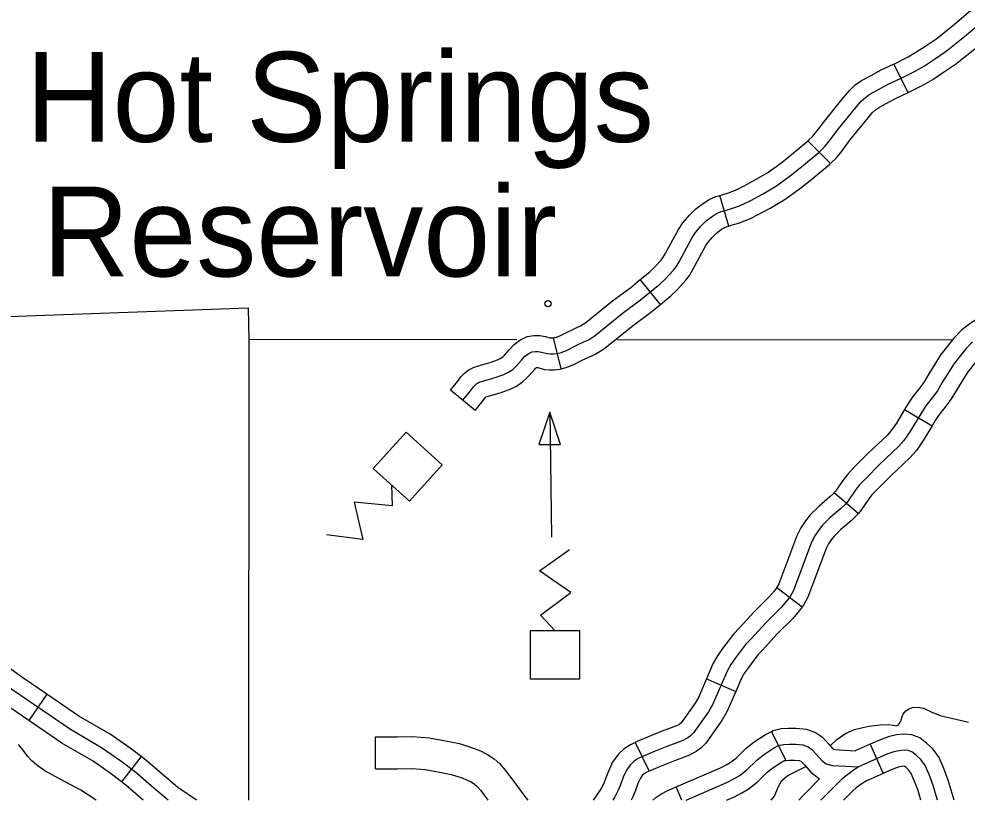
# Model space of a CAD drawing. Extents: x -3711 to 825, y -151 to 1050.
# Drawn here: x -2609.55 to -2559.63, y 120.35 to 161.5 of the extents above; entities that cross this region are included whole.
import ezdxf

# ---------------------------------------------------------------- set-up
doc = ezdxf.new("R2010")
doc.units = 0
for name, color, linetype in [('Level 32', 7, 'Continuous'), ('Level 35', 7, 'Continuous'), ('Level 4', 7, 'Continuous'), ('Level 46', 7, 'Continuous'), ('Level 5', 7, 'Continuous'), ('Level 57', 7, 'Continuous')]:
    doc.layers.add(name, color=color, linetype=linetype)

msp = doc.modelspace()

# ---------------------------------------------------------------- linework, layer by layer
at = {"layer": 'Level 32'}
for p, q in [((-2562.72, 157.628), (-2563.48, 159.128)), ((-2566.815, 153.885), (-2568.004, 155.074)), ((-2572.176, 150.593), (-2572.638, 152.21)), ((-2575.77, 146.466), (-2576.831, 147.77)), ((-2581.001, 143.07), (-2581.409, 144.701)), ((-2585.52, 140.884), (-2586.819, 141.951)), ((-2562.913, 140.934), (-2561.469, 140.074)), ((-2566.618, 136.552), (-2565.347, 135.452)), ((-2569.649, 131.545), (-2568.311, 130.529)), ((-2573.353, 126.732), (-2571.809, 126.066)), ((-2608.085, 125.936), (-2609.037, 124.549)), ((-2569.173, 122.47), (-2569.925, 123.974)), ((-2577.102, 123.391), (-2576.374, 121.876)), ((-2564.732, 123.296), (-2564.052, 121.758)), ((-2603.12, 122.647), (-2604.142, 121.312)), ((-2574.653, 120.355), (-2574.948, 121.043))]:
    msp.add_line(p, q, dxfattribs=at)
for points in [[(-2563.48, 159.128), (-2562.72, 159.514), (-2562.318, 159.749), (-2561.801, 160.091), (-2561.227, 160.48), (-2560.289, 161.231), (-2559.321, 162.053), (-2558.906, 162.446)], [(-2586.169, 141.418), (-2585.769, 141.905), (-2585.618, 142.121), (-2585.531, 142.219), (-2585.434, 142.294), (-2585.272, 142.381), (-2584.818, 142.511), (-2584.418, 142.63), (-2584.018, 142.77), (-2583.78, 142.889), (-2583.553, 143.041), (-2583.369, 143.214), (-2583.088, 143.528), (-2582.904, 143.734), (-2582.731, 143.863), (-2582.525, 143.961), (-2582.352, 143.993), (-2582.212, 143.993), (-2582.028, 143.95), (-2581.736, 143.874), (-2581.585, 143.863), (-2581.401, 143.863), (-2581.206, 143.885), (-2580.99, 143.939), (-2580.687, 144.058), (-2580.309, 144.253), (-2580.028, 144.394), (-2579.768, 144.513), (-2579.595, 144.588), (-2579.39, 144.707), (-2579.195, 144.837), (-2577.779, 145.984), (-2576.816, 146.699), (-2575.778, 147.543), (-2575.497, 147.813), (-2575.081, 148.266), (-2574.946, 148.453), (-2574.791, 148.712), (-2574.102, 149.988), (-2573.929, 150.259), (-2573.638, 150.584), (-2573.356, 150.865), (-2573.032, 151.115), (-2572.814, 151.249), (-2572.576, 151.353), (-2572.287, 151.436), (-2571.924, 151.55), (-2571.659, 151.644), (-2571.378, 151.763), (-2571.01, 151.947), (-2570.405, 152.272), (-2569.659, 152.715), (-2568.848, 153.3), (-2568.231, 153.808), (-2567.41, 154.479), (-2567.128, 154.761), (-2566.869, 155.074), (-2566.458, 155.626), (-2565.647, 156.644), (-2565.215, 157.152), (-2564.98, 157.371), (-2564.739, 157.542), (-2564.285, 157.791), (-2563.777, 158.061), (-2563.128, 158.364), (-2562.317, 158.775), (-2561.874, 159.035), (-2561.333, 159.392), (-2560.727, 159.803), (-2559.754, 160.583), (-2558.76, 161.427)], [(-2562.72, 157.628), (-2561.914, 158.037), (-2561.429, 158.321), (-2560.865, 158.694), (-2560.228, 159.127), (-2559.22, 159.934), (-2558.198, 160.8), (-2557.75, 161.225)], [(-2568.004, 155.074), (-2567.751, 155.327), (-2567.53, 155.594), (-2567.124, 156.139), (-2566.296, 157.178), (-2565.824, 157.734), (-2565.512, 158.024), (-2565.185, 158.256), (-2564.684, 158.53), (-2564.152, 158.814), (-2563.496, 159.12), (-2563.481, 159.128)], [(-2566.815, 153.885), (-2566.506, 154.194), (-2566.207, 154.555), (-2565.792, 155.113), (-2564.998, 156.109), (-2564.606, 156.571), (-2564.448, 156.718), (-2564.292, 156.828), (-2563.885, 157.051), (-2563.401, 157.309), (-2562.76, 157.608), (-2562.72, 157.628)], [(-2572.638, 152.21), (-2572.528, 152.241), (-2572.191, 152.347), (-2571.964, 152.428), (-2571.73, 152.527), (-2571.397, 152.693), (-2570.818, 153.004), (-2570.12, 153.419), (-2569.361, 153.966), (-2568.765, 154.458), (-2567.967, 155.109), (-2567.991, 155.086)], [(-2572.176, 150.593), (-2572.045, 150.631), (-2571.658, 150.752), (-2571.354, 150.86), (-2571.025, 150.999), (-2570.623, 151.201), (-2569.991, 151.54), (-2569.197, 152.012), (-2568.334, 152.634), (-2567.698, 153.159), (-2566.852, 153.849), (-2566.828, 153.873)], [(-2576.831, 147.77), (-2576.336, 148.173), (-2576.099, 148.401), (-2575.733, 148.799), (-2575.649, 148.916), (-2575.522, 149.128), (-2574.827, 150.415), (-2574.601, 150.77), (-2574.248, 151.162), (-2573.912, 151.498), (-2573.511, 151.807), (-2573.206, 151.996), (-2572.861, 152.146), (-2572.638, 152.21)], [(-2575.77, 146.466), (-2575.221, 146.913), (-2574.896, 147.225), (-2574.428, 147.734), (-2574.244, 147.99), (-2574.06, 148.296), (-2573.377, 149.562), (-2573.258, 149.748), (-2573.027, 150.005), (-2572.8, 150.232), (-2572.553, 150.423), (-2572.423, 150.503), (-2572.292, 150.56), (-2572.176, 150.593)], [(-2581.409, 144.701), (-2581.247, 144.741), (-2581.034, 144.825), (-2580.689, 145.003), (-2580.391, 145.152), (-2580.112, 145.28), (-2579.976, 145.34), (-2579.834, 145.421), (-2579.694, 145.515), (-2578.294, 146.649), (-2577.332, 147.363), (-2576.831, 147.77)], [(-2581.001, 143.07), (-2580.733, 143.137), (-2580.34, 143.291), (-2579.928, 143.503), (-2579.664, 143.636), (-2579.424, 143.746), (-2579.215, 143.837), (-2578.945, 143.994), (-2578.696, 144.16), (-2577.263, 145.32), (-2576.301, 146.035), (-2575.77, 146.466)], [(-2558.955, 145.772), (-2559.412, 145.491), (-2559.906, 145.121), (-2560.325, 144.678), (-2561.001, 143.835), (-2561.634, 142.81), (-2561.878, 142.387), (-2562.122, 142.067), (-2562.485, 141.61), (-2562.728, 141.245), (-2562.913, 140.934)], [(-2586.819, 141.951), (-2586.439, 142.413), (-2586.279, 142.643), (-2586.109, 142.834), (-2585.893, 143.002), (-2585.589, 143.165), (-2585.053, 143.318), (-2584.677, 143.43), (-2584.346, 143.546), (-2584.203, 143.618), (-2584.078, 143.701), (-2583.971, 143.802), (-2583.714, 144.089), (-2583.475, 144.356), (-2583.168, 144.587), (-2582.787, 144.767), (-2582.431, 144.834), (-2582.114, 144.834), (-2581.826, 144.766), (-2581.599, 144.707), (-2581.555, 144.704), (-2581.447, 144.704), (-2581.357, 144.714), (-2581.411, 144.7)], [(-2559.344, 144.491), (-2559.69, 144.125), (-2560.313, 143.349), (-2560.912, 142.379), (-2561.176, 141.921), (-2561.458, 141.551), (-2561.805, 141.114), (-2562.017, 140.797), (-2562.639, 139.752), (-2562.956, 139.294), (-2563.237, 138.976), (-2564.224, 138.042), (-2564.982, 137.284), (-2565.285, 136.968), (-2565.477, 136.708), (-2565.88, 136.12), (-2566.054, 135.919), (-2566.285, 135.697), (-2566.849, 135.221), (-2567.254, 134.815), (-2567.457, 134.563), (-2567.649, 134.274), (-2567.813, 133.938), (-2568.774, 131.398), (-2568.947, 131.08), (-2569.13, 130.84), (-2569.418, 130.493), (-2570.244, 129.667), (-2571, 128.848), (-2571.289, 128.546), (-2571.818, 127.84), (-2572.057, 127.5), (-2572.259, 127.147), (-2573.023, 125.375), (-2573.244, 125), (-2574.032, 123.894), (-2574.186, 123.73), (-2574.33, 123.625), (-2574.59, 123.49), (-2575.051, 123.317), (-2575.339, 123.211), (-2576.136, 122.888), (-2576.627, 122.687), (-2576.942, 122.536), (-2577.156, 122.397), (-2577.37, 122.195), (-2577.559, 121.931), (-2577.735, 121.553), (-2577.874, 121.162), (-2578.012, 120.835), (-2578.165, 120.527), (-2578.287, 120.355)], [(-2558.073, 144.341), (-2558.466, 144.099), (-2558.783, 143.861), (-2559.056, 143.573), (-2559.625, 142.863), (-2560.19, 141.948), (-2560.475, 141.455), (-2560.795, 141.034), (-2561.125, 140.619), (-2561.305, 140.349), (-2561.469, 140.074)], [(-2585.52, 140.884), (-2585.099, 141.396), (-2584.961, 141.594), (-2584.955, 141.597), (-2584.582, 141.704), (-2584.158, 141.83), (-2583.689, 141.995), (-2583.357, 142.161), (-2583.027, 142.381), (-2582.766, 142.627), (-2582.461, 142.967), (-2582.333, 143.111), (-2582.294, 143.14), (-2582.282, 143.146), (-2582.23, 143.134), (-2581.873, 143.041), (-2581.615, 143.023), (-2581.354, 143.023), (-2581.056, 143.056), (-2580.998, 143.071)], [(-2562.913, 140.934), (-2563.346, 140.207), (-2563.618, 139.814), (-2563.842, 139.562), (-2564.811, 138.644), (-2565.582, 137.872), (-2565.928, 137.511), (-2566.162, 137.196), (-2566.547, 136.634), (-2566.618, 136.552)], [(-2561.469, 140.074), (-2561.931, 139.298), (-2562.293, 138.774), (-2562.633, 138.391), (-2563.638, 137.44), (-2564.381, 136.696), (-2564.641, 136.425), (-2564.792, 136.22), (-2565.213, 135.606), (-2565.347, 135.452)], [(-2566.618, 136.552), (-2566.664, 136.499), (-2566.848, 136.322), (-2567.418, 135.84), (-2567.881, 135.377), (-2568.136, 135.06), (-2568.381, 134.693), (-2568.586, 134.271), (-2569.54, 131.749), (-2569.655, 131.538), (-2569.649, 131.545)], [(-2565.347, 135.452), (-2565.443, 135.34), (-2565.722, 135.072), (-2566.279, 134.602), (-2566.627, 134.253), (-2566.778, 134.065), (-2566.918, 133.856), (-2567.04, 133.605), (-2568.008, 131.046), (-2568.239, 130.622), (-2568.311, 130.529)], [(-2569.649, 131.545), (-2569.788, 131.363), (-2570.04, 131.061), (-2570.851, 130.25), (-2571.612, 129.424), (-2571.931, 129.091), (-2572.498, 128.334), (-2572.768, 127.951), (-2573.012, 127.523), (-2573.353, 126.732)], [(-2568.311, 130.529), (-2568.472, 130.316), (-2568.797, 129.926), (-2569.638, 129.085), (-2570.387, 128.273), (-2570.647, 128.001), (-2571.138, 127.346), (-2571.347, 127.049), (-2571.505, 126.771), (-2571.809, 126.066)], [(-2608.085, 125.936), (-2609.344, 126.799), (-2612.526, 129.079), (-2613.048, 129.345)], [(-2601.692, 120.355), (-2602.444, 120.985), (-2603.397, 121.801), (-2604.182, 122.401), (-2605.197, 123.109), (-2606.843, 124.064), (-2609.827, 126.111), (-2612.964, 128.359)], [(-2609.037, 124.549), (-2610.309, 125.423), (-2613.403, 127.639), (-2613.813, 127.848)], [(-2573.353, 126.732), (-2573.774, 125.757), (-2573.95, 125.458), (-2574.684, 124.428), (-2574.745, 124.362), (-2574.775, 124.341), (-2574.932, 124.259), (-2575.343, 124.105), (-2575.642, 123.995), (-2576.453, 123.667), (-2576.969, 123.455), (-2577.102, 123.391)], [(-2603.12, 122.647), (-2603.686, 123.08), (-2604.745, 123.819), (-2606.393, 124.775), (-2608.085, 125.936)], [(-2571.809, 126.066), (-2572.272, 124.994), (-2572.538, 124.542), (-2573.381, 123.36), (-2573.626, 123.098), (-2573.885, 122.908), (-2574.247, 122.721), (-2574.758, 122.529), (-2575.037, 122.426), (-2575.819, 122.11), (-2576.285, 121.919), (-2576.374, 121.876)], [(-2604.142, 121.312), (-2604.678, 121.722), (-2605.649, 122.4), (-2607.292, 123.352), (-2609.037, 124.549)], [(-2574.948, 121.043), (-2572.602, 122.049), (-2572.314, 122.202), (-2572.095, 122.332), (-2571.787, 122.564), (-2571.262, 123.088), (-2570.844, 123.414), (-2570.245, 123.813), (-2569.925, 123.974)], [(-2569.928, 123.972), (-2569.836, 124.019), (-2569.416, 124.116), (-2569.027, 124.142), (-2568.623, 124.142), (-2568.087, 124.088), (-2567.609, 123.917), (-2567.247, 123.663), (-2566.923, 123.314), (-2566.698, 123.057), (-2566.674, 123.039), (-2566.582, 123.017), (-2565.51, 122.952)], [(-2560.301, 120.355), (-2560.616, 121.397), (-2560.848, 122.011), (-2561.095, 122.601), (-2561.435, 123.054), (-2561.754, 123.352), (-2562.122, 123.629), (-2562.532, 123.799), (-2562.965, 123.83), (-2563.35, 123.785), (-2563.718, 123.703), (-2564.152, 123.552), (-2564.732, 123.296)], [(-2577.102, 123.391), (-2577.354, 123.27), (-2577.677, 123.061), (-2578.006, 122.751), (-2578.288, 122.356), (-2578.514, 121.872), (-2578.658, 121.466), (-2578.776, 121.186), (-2578.889, 120.959), (-2579.315, 120.355)], [(-2571.626, 121.633), (-2571.234, 121.927), (-2570.705, 122.457), (-2570.352, 122.732), (-2569.822, 123.085), (-2569.548, 123.223), (-2569.293, 123.281), (-2568.999, 123.301), (-2568.665, 123.301), (-2568.273, 123.262), (-2567.999, 123.164), (-2567.803, 123.026), (-2567.548, 122.751), (-2567.273, 122.437), (-2567.038, 122.261), (-2566.704, 122.182), (-2565.336, 122.099)], [(-2561.179, 120.355), (-2561.412, 121.126), (-2561.629, 121.7), (-2561.831, 122.18), (-2562.063, 122.49), (-2562.295, 122.707), (-2562.543, 122.893), (-2562.729, 122.971), (-2562.946, 122.986), (-2563.209, 122.955), (-2563.488, 122.893), (-2563.844, 122.769), (-2565.036, 122.242), (-2565.336, 122.099), (-2565.625, 121.917), (-2565.981, 121.653), (-2566.215, 121.454), (-2567.32, 120.355)], [(-2564.732, 123.296), (-2565.51, 122.952)], [(-2600.208, 120.355), (-2601.181, 121.024), (-2601.901, 121.626), (-2602.868, 122.454), (-2603.12, 122.647)], [(-2572.287, 120.355), (-2571.876, 120.531), (-2571.489, 120.736), (-2571.157, 120.934), (-2570.682, 121.291), (-2570.147, 121.826), (-2569.86, 122.05), (-2569.399, 122.357), (-2569.173, 122.47)], [(-2569.26, 122.426), (-2569.17, 122.447), (-2568.971, 122.46), (-2568.707, 122.46), (-2568.459, 122.436), (-2568.388, 122.41), (-2568.358, 122.389), (-2568.172, 122.189), (-2567.848, 121.818), (-2567.388, 121.473)], [(-2576.374, 121.876), (-2576.53, 121.801), (-2576.635, 121.733), (-2576.734, 121.64), (-2576.83, 121.505), (-2576.956, 121.234), (-2577.089, 120.858), (-2577.247, 120.483), (-2577.312, 120.355)], [(-2562.057, 120.355), (-2562.209, 120.856), (-2562.41, 121.389), (-2562.566, 121.759), (-2562.691, 121.927), (-2562.836, 122.062), (-2562.94, 122.14), (-2563.068, 122.125), (-2563.257, 122.083), (-2563.535, 121.987), (-2564.052, 121.758)], [(-2603.001, 120.355), (-2603.927, 121.147), (-2604.142, 121.312)], [(-2574.419, 120.355), (-2572.239, 121.29), (-2571.901, 121.469), (-2571.626, 121.633)], [(-2567.388, 121.473), (-2567.998, 120.866), (-2568.234, 120.618), (-2568.479, 120.355)], [(-2564.052, 121.758), (-2564.685, 121.478), (-2564.929, 121.362), (-2565.149, 121.223), (-2565.458, 120.995), (-2565.645, 120.835), (-2566.128, 120.355)], [(-2576.172, 120.355), (-2576.021, 120.482), (-2575.743, 120.664), (-2575.381, 120.857), (-2574.948, 121.043)]]:
    msp.add_lwpolyline(points, dxfattribs=at)
at = {"layer": 'Level 35'}
for points in [[(-2566.839, 123.218), (-2566.487, 123.552), (-2566.238, 123.724), (-2565.994, 123.878), (-2565.551, 124.068), (-2565.111, 124.183), (-2564.791, 124.248), (-2564.204, 124.31), (-2563.739, 124.343), (-2563.51, 124.294), (-2563.335, 124.26), (-2563.233, 124.311), (-2563.115, 124.514), (-2563.048, 124.733), (-2562.983, 124.883), (-2562.845, 125.054), (-2562.719, 125.146), (-2562.522, 125.234), (-2562.236, 125.256), (-2561.929, 125.19), (-2561.49, 124.993), (-2560.985, 124.795), (-2560.524, 124.685), (-2559.558, 124.465)], [(-2605.49, 120.355), (-2606.295, 120.878), (-2607.414, 121.48), (-2608.182, 121.895), (-2608.617, 122.186), (-2608.866, 122.414), (-2609.094, 122.663), (-2609.322, 122.975), (-2609.571, 123.286)], [(-2569.935, 120.355), (-2569.764, 120.565), (-2569.579, 121.028), (-2569.394, 121.367), (-2569.117, 121.614), (-2568.817, 121.774), (-2568.112, 122.12)]]:
    msp.add_lwpolyline(points, dxfattribs=at)
at = {"layer": 'Level 4'}
msp.add_lwpolyline([(-2597.488, 146.288), (-2597.451, 144.624), (-2597.463, 120.355)], dxfattribs=at)
at = {"layer": 'Level 46'}
for points in [[(-2590.768, 122.008), (-2590.768, 123.689), (-2589.633, 123.689), (-2588.823, 123.705), (-2587.947, 123.637), (-2587.082, 123.482), (-2586.36, 123.326), (-2585.724, 123.125), (-2585.246, 122.948), (-2584.884, 122.762), (-2584.536, 122.534), (-2584.225, 122.256), (-2583.945, 121.935), (-2583.493, 121.337), (-2582.909, 120.542), (-2582.755, 120.355)], [(-2590.768, 122.008), (-2589.616, 122.008), (-2588.871, 122.022), (-2588.161, 121.968), (-2587.408, 121.832), (-2586.792, 121.699), (-2586.27, 121.534), (-2585.924, 121.406), (-2585.731, 121.307), (-2585.563, 121.197), (-2585.422, 121.071), (-2585.25, 120.874), (-2584.859, 120.355)]]:
    msp.add_lwpolyline(points, dxfattribs=at)
at = {"layer": 'Level 5'}
for points in [[(-2623.24, 145.353), (-2597.488, 146.288)], [(-2583.33, 144.606), (-2597.451, 144.624)], [(-2560.426, 144.576), (-2578.039, 144.599)]]:
    msp.add_lwpolyline(points, dxfattribs=at)
at = {"layer": 'Level 57'}
msp.add_line((-2581.603, 140.793), (-2581.501, 134.2), dxfattribs=at)
for points in [[(-2582.179, 139.08), (-2581.036, 139.077), (-2581.603, 140.793)], [(-2587.259, 138.014), (-2588.982, 136.104), (-2590.892, 137.827), (-2589.168, 139.737)], [(-2582.612, 126.717), (-2582.612, 129.289), (-2580.039, 129.289), (-2580.039, 126.717)]]:
    msp.add_lwpolyline(points, close=True, dxfattribs=at)
for points in [[(-2589.937, 136.966), (-2589.903, 135.858), (-2591.907, 136.04), (-2591.438, 134.086), (-2593.361, 134.323)], [(-2581.326, 129.289), (-2582.093, 130.089), (-2580.483, 131.296), (-2582.14, 132.433), (-2580.554, 133.545)]]:
    msp.add_lwpolyline(points, dxfattribs=at)
msp.add_circle((-2581.691, 146.504), 0.168, dxfattribs=at)

# ---------------------------------------------------------------- texts
at = {"layer": 'Level 35'}
for s, height, p in [('Hot Springs', 4.73431, (-2609.194, 155.03)), ('Reservoir', 4.7343, (-2608.309, 147.94))]:
    msp.add_text(s, height=height, dxfattribs=at).set_placement(p)

doc.saveas('drawing.dxf')
